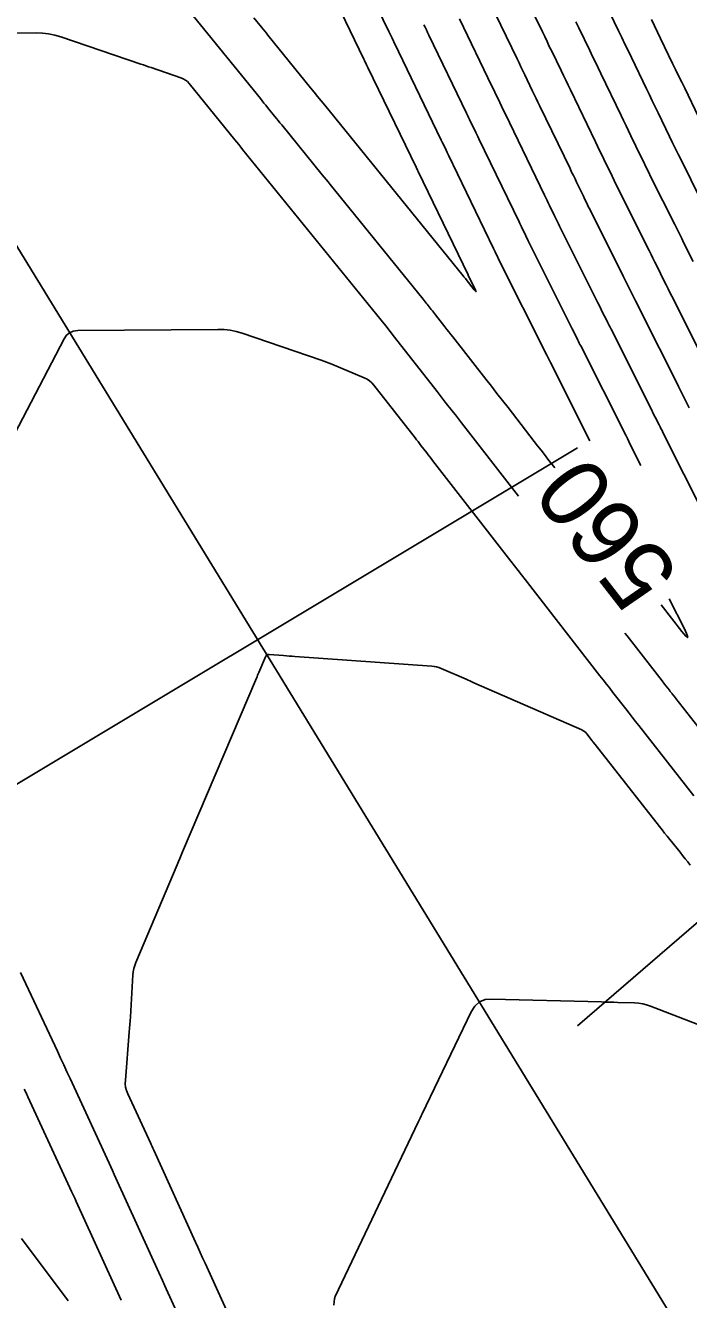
# Model space of a CAD drawing. Extents: x 954385 to 988206, y 1868364 to 1924553.
# Drawn here: x 957159.4 to 957216.7, y 1920795.3 to 1920905.5 of the extents above; entities that cross this region are included whole.
import ezdxf

# ---------------------------------------------------------------- set-up
doc = ezdxf.new("R2010")
doc.units = 0
for name, color, linetype in [('26', 7, 'Continuous'), ('5', 7, 'Continuous'), ('6', 7, 'Continuous'), ('7', 7, 'Continuous'), ('Default', 7, 'Continuous')]:
    doc.layers.add(name, color=color, linetype=linetype)

msp = doc.modelspace()

# ---------------------------------------------------------------- linework, layer by layer
at = {"layer": '26'}
for points in [[(957207.13, 1920868.93), (957087.13, 1920796.9), (957090.04, 1920802.14), (957087.13, 1920796.9), (957093.13, 1920797)], [(957207.13, 1920818.93), (957244.79, 1920851.42), (957242.81, 1920845.76), (957244.79, 1920851.42), (957238.89, 1920850.3)]]:
    msp.add_lwpolyline(points, dxfattribs=at)
at = {"layer": '6'}
for points in [[(957187.32, 1920912.19), (957190.83, 1920904.93), (957190.97, 1920904.64), (957191.1, 1920904.36), (957191.38, 1920903.79), (957191.51, 1920903.51), (957191.65, 1920903.22), (957195.36, 1920895.53), (957195.47, 1920895.32), (957195.57, 1920895.1), (957195.78, 1920894.67), (957195.88, 1920894.46), (957195.98, 1920894.24), (957199.88, 1920886.18), (957200.02, 1920885.87), (957200.17, 1920885.56), (957200.21, 1920885.48), (957200.25, 1920885.4), (957200.29, 1920885.33), (957200.32, 1920885.25), (957204.47, 1920876.95), (957204.68, 1920876.53), (957204.71, 1920876.48), (957204.73, 1920876.43), (957204.76, 1920876.37), (957204.79, 1920876.32), (957208.19, 1920869.54)], [(957205.18, 1920867.19), (957204.58, 1920867.96), (957204.28, 1920868.34), (957203.99, 1920868.72), (957203.69, 1920869.1), (957203.4, 1920869.48), (957201.13, 1920872.41), (957200.65, 1920873.02), (957200.17, 1920873.63), (957199.69, 1920874.25), (957199.21, 1920874.86), (957196.35, 1920878.52), (957196.18, 1920878.73), (957196.02, 1920878.95), (957195.85, 1920879.16), (957195.68, 1920879.38), (957194.86, 1920880.43), (957194.77, 1920880.54), (957194.68, 1920880.66), (957194.59, 1920880.77), (957194.5, 1920880.88), (957194.15, 1920881.34), (957194.06, 1920881.45), (957193.97, 1920881.56), (957193.88, 1920881.68), (957193.79, 1920881.79), (957185.75, 1920891.71), (957185.57, 1920891.92), (957185.4, 1920892.13), (957185.23, 1920892.34), (957185.06, 1920892.55), (957181.57, 1920896.86), (957181.41, 1920897.05), (957181.26, 1920897.23), (957181.11, 1920897.42), (957180.95, 1920897.61), (957180.34, 1920898.37), (957180.19, 1920898.56), (957180.03, 1920898.75), (957179.88, 1920898.94), (957179.73, 1920899.13), (957169.36, 1920911.9)], [(957217.13, 1920885.05), (957216.34, 1920886.64), (957216.14, 1920887.04), (957215.94, 1920887.44), (957215.74, 1920887.84), (957215.54, 1920888.23), (957213.48, 1920892.35), (957213.26, 1920892.79), (957213.05, 1920893.23), (957212.83, 1920893.68), (957212.61, 1920894.12), (957211.76, 1920895.9), (957211.54, 1920896.35), (957211.33, 1920896.79), (957211.11, 1920897.23), (957210.9, 1920897.68), (957209.16, 1920901.29), (957208.92, 1920901.79), (957208.68, 1920902.28), (957208.44, 1920902.78), (957208.2, 1920903.28), (957207.24, 1920905.26), (957207, 1920905.76)], [(957215.05, 1920855.87), (957216.4, 1920853.2), (957216.62, 1920852.71), (957216.66, 1920852.52), (957216.51, 1920852.64), (957216.16, 1920853.05), (957214.38, 1920855.35)]]:
    msp.add_lwpolyline(points, dxfattribs=at)
at = {"layer": '7'}
for points in [[(957179.16, 1920906.12), (957179.82, 1920905.3), (957179.96, 1920905.13), (957180.1, 1920904.96), (957180.24, 1920904.79), (957180.38, 1920904.62), (957184.06, 1920900.07), (957184.37, 1920899.7), (957184.67, 1920899.32), (957184.98, 1920898.95), (957185.28, 1920898.57), (957197.25, 1920883.81), (957197.32, 1920883.73), (957197.38, 1920883.65), (957197.45, 1920883.57), (957197.51, 1920883.49), (957198.21, 1920882.59), (957198.32, 1920882.47), (957198.37, 1920882.43), (957198.36, 1920882.49), (957198.29, 1920882.64), (957197.69, 1920883.83), (957197.68, 1920883.85), (957197.67, 1920883.88), (957193.35, 1920892.83), (957193.29, 1920892.95), (957193.18, 1920893.19), (957189.01, 1920901.82), (957188.9, 1920902.06), (957188.73, 1920902.42), (957188.67, 1920902.53), (957184.68, 1920910.81)], [(957202.21, 1920908.83), (957204.1, 1920904.91), (957204.3, 1920904.49), (957204.5, 1920904.07), (957204.7, 1920903.65), (957204.91, 1920903.23), (957205.71, 1920901.56), (957205.92, 1920901.14), (957206.12, 1920900.72), (957206.32, 1920900.3), (957206.52, 1920899.88), (957208.69, 1920895.38), (957208.87, 1920895.01), (957209.05, 1920894.64), (957209.23, 1920894.27), (957209.41, 1920893.89), (957210.13, 1920892.41), (957210.31, 1920892.04), (957210.49, 1920891.67), (957210.67, 1920891.3), (957210.85, 1920890.93), (957213.33, 1920885.98), (957213.49, 1920885.65), (957213.65, 1920885.32), (957213.82, 1920884.99), (957213.98, 1920884.66), (957214.64, 1920883.35), (957214.8, 1920883.02), (957214.97, 1920882.69), (957215.13, 1920882.36), (957215.3, 1920882.03), (957217.97, 1920876.71)], [(957216.8, 1920872.39), (957216.68, 1920872.62), (957216.21, 1920873.55), (957216.1, 1920873.78), (957215.98, 1920874.01), (957215.86, 1920874.24), (957215.75, 1920874.48), (957212.67, 1920880.6), (957212.54, 1920880.86), (957212.41, 1920881.12), (957212.28, 1920881.38), (957212.15, 1920881.64), (957211.63, 1920882.68), (957211.37, 1920883.2), (957211.11, 1920883.72), (957208.22, 1920889.51), (957208.07, 1920889.81), (957207.93, 1920890.1), (957207.78, 1920890.4), (957207.64, 1920890.7), (957207.06, 1920891.89), (957206.92, 1920892.19), (957206.78, 1920892.48), (957206.63, 1920892.78), (957206.49, 1920893.08), (957203.89, 1920898.47), (957203.72, 1920898.81), (957203.56, 1920899.15), (957203.39, 1920899.49), (957203.23, 1920899.84), (957202.57, 1920901.2), (957202.41, 1920901.54), (957202.24, 1920901.88), (957202.08, 1920902.22), (957201.91, 1920902.56), (957199.57, 1920907.43)], [(957217.75, 1920890.49), (957216.12, 1920893.77), (957215.86, 1920894.28), (957215.61, 1920894.8), (957215.35, 1920895.32), (957215.1, 1920895.84), (957214.1, 1920897.91), (957213.85, 1920898.43), (957213.6, 1920898.94), (957213.35, 1920899.46), (957213.1, 1920899.98), (957211.79, 1920902.7), (957211.51, 1920903.28), (957211.24, 1920903.85), (957210.96, 1920904.42), (957210.68, 1920905), (957209.56, 1920907.33)], [(957212.61, 1920867.41), (957211.89, 1920868.82), (957211.79, 1920869.02), (957211.7, 1920869.22), (957211.45, 1920869.72), (957211.3, 1920870.01), (957207.41, 1920877.75), (957207.35, 1920877.87), (957207.29, 1920877.99), (957207.23, 1920878.11), (957207.17, 1920878.23), (957206.87, 1920878.84), (957206.68, 1920879.21), (957202.96, 1920886.67), (957202.88, 1920886.82), (957202.81, 1920886.97), (957202.73, 1920887.12), (957202.66, 1920887.27), (957202.3, 1920888.03), (957202.15, 1920888.33), (957202.08, 1920888.48), (957198.62, 1920895.65), (957198.53, 1920895.84), (957198.44, 1920896.02), (957198.35, 1920896.21), (957198.26, 1920896.39), (957197.9, 1920897.13), (957197.81, 1920897.32), (957197.72, 1920897.51), (957197.63, 1920897.69), (957197.55, 1920897.88), (957194.29, 1920904.62), (957194.18, 1920904.85), (957194.07, 1920905.07), (957193.96, 1920905.3), (957193.86, 1920905.52)], [(957196.93, 1920906.02), (957199.73, 1920900.22), (957199.86, 1920899.96), (957199.98, 1920899.69), (957200.11, 1920899.43), (957200.24, 1920899.17), (957200.75, 1920898.11), (957200.87, 1920897.85), (957201, 1920897.59), (957201.13, 1920897.32), (957201.25, 1920897.06), (957204.28, 1920890.78), (957204.39, 1920890.55), (957204.5, 1920890.33), (957204.61, 1920890.11), (957204.72, 1920889.88), (957205.15, 1920888.98), (957205.26, 1920888.76), (957205.37, 1920888.54), (957205.48, 1920888.31), (957205.59, 1920888.09), (957208.9, 1920881.47), (957209.09, 1920881.08), (957209.28, 1920880.7), (957209.66, 1920879.94), (957209.76, 1920879.75), (957209.85, 1920879.56), (957209.95, 1920879.37), (957210.04, 1920879.18), (957213.52, 1920872.24), (957213.69, 1920871.91), (957213.85, 1920871.58), (957214.19, 1920870.92), (957214.27, 1920870.75), (957214.35, 1920870.59), (957214.44, 1920870.42), (957214.52, 1920870.26), (957218.14, 1920863.04)], [(957217.59, 1920897.55), (957216.4, 1920900.02), (957216.14, 1920900.56), (957215.88, 1920901.1), (957215.62, 1920901.64), (957215.36, 1920902.18), (957214.32, 1920904.34), (957214.05, 1920904.88), (957213.79, 1920905.42), (957213.53, 1920905.96)], [(957156.79, 1920904.78), (957160.34, 1920904.81), (957160.88, 1920904.79), (957161.42, 1920904.73), (957161.94, 1920904.62), (957162.46, 1920904.47), (957169.39, 1920902.11), (957169.61, 1920902.04), (957169.83, 1920901.96), (957170.05, 1920901.89), (957170.27, 1920901.81), (957172.85, 1920900.93), (957173.06, 1920900.85), (957173.24, 1920900.74), (957173.41, 1920900.6), (957173.56, 1920900.44), (957177.51, 1920895.56), (957177.68, 1920895.35), (957177.85, 1920895.15), (957178.02, 1920894.94), (957178.19, 1920894.73), (957189.78, 1920880.44), (957190.17, 1920879.96), (957190.56, 1920879.47), (957190.94, 1920878.99), (957191.32, 1920878.5), (957195.01, 1920873.79), (957195.18, 1920873.56), (957195.36, 1920873.34), (957195.53, 1920873.11), (957195.71, 1920872.89), (957196.41, 1920871.99), (957196.58, 1920871.77), (957196.76, 1920871.55), (957196.93, 1920871.32), (957197.11, 1920871.1), (957202.04, 1920864.75)], [(957217.2, 1920838.83), (957212.43, 1920844.91), (957212.15, 1920845.26), (957211.87, 1920845.62), (957211.59, 1920845.98), (957211.31, 1920846.34), (957210.19, 1920847.77), (957209.92, 1920848.13), (957209.64, 1920848.49), (957209.36, 1920848.85), (957209.08, 1920849.21), (957202.61, 1920857.53), (957202.3, 1920857.93), (957202, 1920858.33), (957201.69, 1920858.72), (957201.38, 1920859.12), (957194.61, 1920867.83), (957194.49, 1920867.99), (957194.36, 1920868.16), (957194.23, 1920868.32), (957194.11, 1920868.48), (957193.6, 1920869.13), (957193.47, 1920869.3), (957193.35, 1920869.46), (957193.22, 1920869.62), (957193.09, 1920869.78), (957189.52, 1920874.35), (957189.35, 1920874.55), (957189.15, 1920874.72), (957188.94, 1920874.86), (957188.7, 1920874.98), (957185.89, 1920876.16), (957185.67, 1920876.25), (957185.44, 1920876.34), (957185.22, 1920876.42), (957184.99, 1920876.5), (957178.14, 1920878.83), (957177.63, 1920878.98), (957177.11, 1920879.09), (957176.58, 1920879.15), (957176.04, 1920879.17), (957163.93, 1920879.07), (957163.55, 1920879.02), (957163.23, 1920878.88), (957162.96, 1920878.66), (957162.75, 1920878.35), (957150.64, 1920855.12)], [(957211.24, 1920852.91), (957211.43, 1920852.66), (957214.46, 1920848.76), (957214.66, 1920848.5), (957215.08, 1920847.96), (957215.16, 1920847.86), (957215.24, 1920847.76), (957215.26, 1920847.73), (957215.28, 1920847.71), (957215.3, 1920847.68), (957215.32, 1920847.66), (957215.6, 1920847.29), (957215.64, 1920847.24), (957220.72, 1920840.78)], [(957178.07, 1920791.54), (957174.94, 1920798.42), (957174.73, 1920798.87), (957174.53, 1920799.33), (957174.32, 1920799.78), (957174.11, 1920800.23), (957170.5, 1920808.18), (957170.43, 1920808.34), (957170.36, 1920808.5), (957170.28, 1920808.66), (957170.21, 1920808.81), (957168.25, 1920813.06), (957168.14, 1920813.34), (957168.07, 1920813.63), (957168.04, 1920813.93), (957168.05, 1920814.23), (957168.39, 1920818.4), (957168.42, 1920818.73), (957168.44, 1920819.05), (957168.47, 1920819.38), (957168.49, 1920819.71), (957168.71, 1920823.34), (957168.73, 1920823.61), (957168.78, 1920823.89), (957168.86, 1920824.15), (957168.96, 1920824.41), (957172.53, 1920832.87), (957172.65, 1920833.14), (957172.76, 1920833.42), (957172.88, 1920833.69), (957172.99, 1920833.97), (957179.38, 1920849.01), (957179.43, 1920849.13), (957179.48, 1920849.25), (957179.54, 1920849.38), (957179.59, 1920849.5), (957180.16, 1920850.86), (957180.21, 1920850.95), (957180.29, 1920851.01), (957180.37, 1920851.04), (957180.48, 1920851.05), (957181.72, 1920850.96), (957181.97, 1920850.94), (957182.21, 1920850.92), (957182.46, 1920850.91), (957182.7, 1920850.89), (957194.54, 1920850.05), (957194.75, 1920850.02), (957194.95, 1920849.98), (957195.15, 1920849.92), (957195.35, 1920849.85), (957197.5, 1920848.91), (957197.67, 1920848.83), (957197.84, 1920848.76), (957198.01, 1920848.69), (957198.17, 1920848.61), (957207.51, 1920844.53), (957207.63, 1920844.46), (957207.75, 1920844.39), (957207.85, 1920844.3), (957207.94, 1920844.19), (957208.41, 1920843.58), (957208.43, 1920843.56), (957208.45, 1920843.53), (957208.47, 1920843.51), (957208.49, 1920843.48), (957208.66, 1920843.27), (957214.23, 1920836.17), (957214.45, 1920835.89), (957214.67, 1920835.61), (957214.89, 1920835.34), (957215.11, 1920835.06), (957216, 1920833.95), (957216.22, 1920833.67), (957216.44, 1920833.39), (957216.66, 1920833.11), (957216.88, 1920832.83)], [(957158.98, 1920823.56), (957162.18, 1920816.73), (957162.45, 1920816.14), (957162.72, 1920815.55), (957163, 1920814.96), (957163.27, 1920814.38), (957166.65, 1920807.05), (957166.8, 1920806.73), (957166.94, 1920806.41), (957167.09, 1920806.09), (957167.24, 1920805.77), (957171.09, 1920797.29), (957171.14, 1920797.18), (957171.59, 1920796.19), (957175.06, 1920788.56)], [(957222.42, 1920817.19), (957213.45, 1920820.64), (957213.11, 1920820.76), (957212.77, 1920820.84), (957212.42, 1920820.89), (957212.06, 1920820.92), (957210.63, 1920820.96), (957210.27, 1920820.97), (957209.91, 1920820.98), (957209.56, 1920820.99), (957209.2, 1920821), (957199.73, 1920821.25), (957199.14, 1920821.2), (957198.65, 1920821), (957198.25, 1920820.65), (957197.93, 1920820.16), (957193.71, 1920811.32), (957193.62, 1920811.14), (957193.54, 1920810.96), (957193.45, 1920810.78), (957193.36, 1920810.6), (957186.19, 1920795.52), (957186.17, 1920795.48), (957186.16, 1920795.44), (957186.15, 1920795.4), (957186.14, 1920795.36), (957186.08, 1920794.77)], [(957167.68, 1920795.2), (957163.8, 1920803.73), (957163.67, 1920804.03), (957163.53, 1920804.32), (957163.4, 1920804.62), (957163.26, 1920804.91), (957159.62, 1920812.8), (957159.47, 1920813.13), (957159.31, 1920813.46)], [(957159.08, 1920800.54), (957163.12, 1920795.14)]]:
    msp.add_lwpolyline(points, dxfattribs=at)
at = {"layer": 'Default'}
msp.add_line((957221.14, 1920784.24), (956045.8, 1922705.18), dxfattribs=at)

# ---------------------------------------------------------------- texts
at = {"layer": '5'}
msp.add_text('560', height=6, rotation=127.8394, dxfattribs=at).set_placement((957216.09, 1920858.03))

doc.saveas('drawing.dxf')
